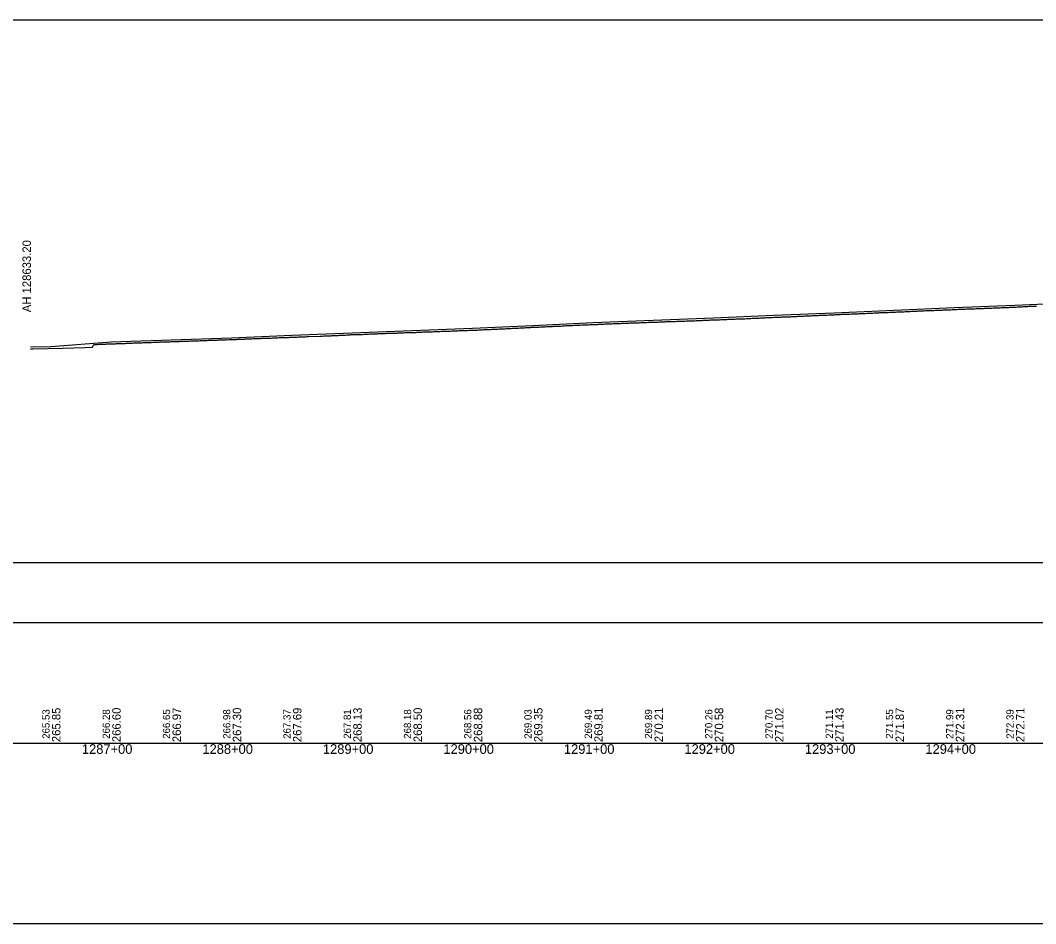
# Model space of a CAD drawing. Extents: x 2898 to 49495, y -15038 to -13538.
# Drawn here: x 18078 to 18921, y -15038 to -14288 of the extents above; entities that cross this region are included whole.
import ezdxf

# ---------------------------------------------------------------- set-up
doc = ezdxf.new("R2010")
doc.units = 0
for name, color, linetype in [('RD_DDB_Profile_EX', 7, 'Continuous'), ('RD_DDB_Profile_PR', 7, 'Continuous'), ('RD_DDB_StaTX', 7, 'Continuous'), ('RD_DDB_StripGrade', 7, 'Continuous'), ('RD_GPK_Profile_Cell', 7, 'Continuous'), ('RD_SHT_ShtClip', 7, 'Continuous')]:
    doc.layers.add(name, color=color, linetype=linetype)

msp = doc.modelspace()

# ---------------------------------------------------------------- linework, layer by layer
at = {"layer": 'RD_DDB_Profile_EX'}
for points in [[(18834.26, -14529.37), (18835.26, -14529.27), (18836.25, -14529.27), (18837.25, -14529.22), (18838.26, -14529.22), (18839.26, -14529.17), (18840.26, -14529.07), (18841.26, -14529.02), (18842.26, -14529.02), (18843.25, -14529.02), (18844.26, -14528.97), (18845.26, -14528.92), (18846.26, -14528.82), (18847.26, -14528.77), (18848.26, -14528.77), (18849.25, -14528.77), (18850.25, -14528.72), (18851.26, -14528.67), (18852.26, -14528.62), (18853.26, -14528.52), (18854.26, -14528.52), (18855.26, -14528.47), (18856.25, -14528.42), (18857.26, -14528.37), (18858.26, -14528.37), (18859.26, -14528.32), (18860.26, -14528.32), (18861.26, -14528.27), (18862.26, -14528.17), (18863.25, -14528.12), (18864.26, -14528.07), (18865.26, -14528.12), (18866.26, -14528.07), (18867.26, -14528.02), (18868.26, -14527.92), (18869.25, -14527.92), (18870.26, -14527.88), (18871.26, -14527.83), (18872.26, -14527.83), (18873.26, -14527.78), (18874.26, -14527.73), (18875.26, -14527.73), (18876.26, -14527.68), (18877.26, -14527.63), (18878.25, -14527.48), (18879.26, -14527.48), (18880.26, -14527.48), (18881.26, -14527.43), (18882.26, -14527.43), (18883.26, -14527.38), (18884.27, -14527.33), (18885.26, -14527.28), (18886.26, -14527.23), (18887.26, -14527.17), (18888.26, -14527.13), (18889.26, -14527.08), (18890.26, -14527.07), (18891.26, -14527.12), (18892.26, -14526.97), (18893.26, -14526.87), (18894.26, -14526.88), (18895.26, -14526.87), (18896.26, -14526.82), (18897.25, -14526.82), (18898.26, -14526.77), (18899.25, -14526.62), (18900.26, -14526.62), (18901.26, -14526.57), (18902.26, -14526.53), (18903.26, -14526.52), (18904.26, -14526.52), (18905.26, -14526.47), (18906.26, -14526.37), (18907.26, -14526.33), (18908.26, -14526.27), (18909.26, -14526.22), (18910.26, -14526.17), (18911.26, -14526.17), (18912.26, -14526.12), (18913.26, -14526.07), (18914.26, -14525.97), (18915.26, -14525.92), (18916.25, -14525.92), (18917.26, -14525.92), (18918.25, -14525.92), (18919.26, -14525.82), (18920.25, -14525.72), (18921.26, -14525.67)], [(18639.8, -14537.74), (18640.8, -14537.76), (18641.8, -14537.71), (18642.81, -14537.61), (18643.8, -14537.6), (18644.8, -14537.55), (18645.8, -14537.51), (18646.8, -14537.44), (18647.8, -14537.39), (18648.8, -14537.34), (18649.8, -14537.3), (18650.8, -14537.25), (18651.81, -14537.25), (18652.8, -14537.24), (18653.8, -14537.14), (18654.8, -14537.09), (18655.8, -14537.09), (18656.8, -14537.07), (18657.43, -14537.07), (18658.42, -14537.03), (18659.42, -14536.94), (18660.43, -14536.92), (18661.43, -14536.89), (18662.42, -14536.84), (18663.43, -14536.79), (18664.42, -14536.74), (18665.42, -14536.69), (18666.42, -14536.68), (18667.42, -14536.64), (18668.42, -14536.57), (18669.43, -14536.52), (18670.43, -14536.47), (18671.42, -14536.47), (18672.33, -14536.38), (18673.33, -14536.38), (18674.33, -14536.37), (18675.33, -14536.28), (18676.33, -14536.24), (18677.33, -14536.18), (18678.33, -14536.18), (18679.33, -14536.17), (18680.33, -14536.03), (18681.33, -14535.98), (18682.33, -14535.93), (18683.33, -14535.97), (18684.33, -14535.97), (18685.33, -14535.88), (18686.33, -14535.78), (18687.33, -14535.73), (18688.33, -14535.72), (18689.33, -14535.72), (18690.33, -14535.67), (18691.33, -14535.62), (18692.33, -14535.58), (18693.33, -14535.52), (18694.33, -14535.47), (18695.33, -14535.39), (18696.33, -14535.37), (18697.33, -14535.33), (18698.33, -14535.33), (18699.33, -14535.27), (18700.33, -14535.14), (18701.33, -14535.17), (18702.33, -14535.15), (18703.33, -14534.97), (18704.33, -14534.93), (18705.33, -14534.88), (18706.4, -14534.89), (18707.4, -14534.88), (18708.4, -14534.82), (18709.4, -14534.81), (18710.4, -14534.71), (18711.4, -14534.71), (18712.4, -14534.62), (18713.4, -14534.57), (18714.4, -14534.53), (18715.4, -14534.52), (18716.4, -14534.52), (18717.4, -14534.52), (18718.4, -14534.38), (18719.4, -14534.28), (18720.4, -14534.33), (18721.4, -14534.32), (18722.4, -14534.27), (18723.4, -14534.18), (18724.4, -14534.13), (18725.4, -14534.16), (18726.4, -14534.08), (18727.4, -14533.98), (18728.39, -14533.98), (18729.39, -14533.92), (18730.39, -14533.92), (18731.39, -14533.84), (18732.39, -14533.79), (18733.39, -14533.78), (18734.39, -14533.72), (18735.39, -14533.58), (18736.39, -14533.58), (18737.39, -14533.62), (18738.39, -14533.62), (18739.39, -14533.58)], [(18739.39, -14533.58), (18740.39, -14533.47), (18741.39, -14533.38), (18742.39, -14533.34), (18743.39, -14533.33), (18744.39, -14533.28), (18745.39, -14533.23), (18746.39, -14533.17), (18747.39, -14533.17), (18748.62, -14533.07), (18749.62, -14533.07), (18750.62, -14533.02), (18751.62, -14532.97), (18752.62, -14532.97), (18753.61, -14532.87), (18754.61, -14532.83), (18755.61, -14532.82), (18756.61, -14532.77), (18757.61, -14532.72), (18758.6, -14532.62), (18759.6, -14532.53), (18760.6, -14532.53), (18761.6, -14532.52), (18762.6, -14532.52), (18763.6, -14532.47), (18764.59, -14532.42), (18765.59, -14532.37), (18766.59, -14532.37), (18767.58, -14532.27), (18768.58, -14532.22), (18769.58, -14532.17), (18770.58, -14532.07), (18771.58, -14532.02), (18772.57, -14532.07), (18773.57, -14532.02), (18774.57, -14531.97), (18775.56, -14531.92), (18776.56, -14531.91), (18777.56, -14531.87), (18778.56, -14531.81), (18779.56, -14531.77), (18780.56, -14531.72), (18781.55, -14531.62), (18782.55, -14531.57), (18783.55, -14531.52), (18784.54, -14531.52), (18785.54, -14531.47), (18786.54, -14531.42), (18787.55, -14531.37), (18788.26, -14531.37), (18789.26, -14531.27), (18790.26, -14531.22), (18790.62, -14531.2), (18791.26, -14531.17), (18791.63, -14531.15), (18792.26, -14531.12), (18793.26, -14531.12), (18794.25, -14531.12), (18795.26, -14531.07), (18796.26, -14530.97), (18797.37, -14530.92), (18798.26, -14530.92), (18799.26, -14530.87), (18799.89, -14530.83), (18800.26, -14530.82), (18801.25, -14530.77), (18801.58, -14530.75), (18802.26, -14530.72), (18802.57, -14530.72), (18803.26, -14530.72), (18804.25, -14530.67), (18805.32, -14530.62), (18806.46, -14530.6), (18807.26, -14530.57), (18808.26, -14530.47), (18809.26, -14530.42), (18810.26, -14530.37), (18811.25, -14530.37), (18812.26, -14530.27), (18813.25, -14530.27), (18814.25, -14530.27), (18815.26, -14530.22), (18816.26, -14530.12), (18817.26, -14530.07), (18818.41, -14530.06), (18819.26, -14530.02), (18820.26, -14529.97), (18821.25, -14529.87), (18822.26, -14529.82), (18823.25, -14529.77), (18824.26, -14529.72), (18825.26, -14529.67), (18826.26, -14529.67), (18827.26, -14529.67), (18828.26, -14529.57), (18829.25, -14529.52), (18830.25, -14529.52), (18831.26, -14529.42), (18832.26, -14529.37), (18833.26, -14529.37), (18834.26, -14529.37)], [(18440.2, -14546.27), (18441.2, -14546.18), (18442.17, -14546.09), (18443.18, -14546.08), (18444.18, -14546.08), (18445.18, -14546.03), (18446.18, -14545.98), (18447.18, -14545.93), (18448.18, -14545.93), (18449.18, -14545.88), (18450.46, -14545.79), (18451.45, -14545.75), (18452.45, -14545.73), (18453.45, -14545.69), (18454.45, -14545.63), (18455.45, -14545.63), (18456.45, -14545.64), (18457.45, -14545.63), (18458.45, -14545.43), (18459.46, -14545.43), (18460.45, -14545.39), (18461.45, -14545.35), (18462.45, -14545.3), (18463.45, -14545.3), (18464.45, -14545.2), (18465.45, -14545.19), (18466.45, -14545.19), (18467.45, -14545.16), (18468.45, -14545.04), (18469.45, -14544.9), (18470.46, -14544.85), (18471.46, -14544.89), (18472.45, -14544.84), (18473.46, -14544.75), (18474.45, -14544.75), (18475.45, -14544.7), (18476.46, -14544.64), (18477.45, -14544.63), (18478.45, -14544.59), (18479.45, -14544.6), (18480.45, -14544.49), (18481.45, -14544.44), (18482.46, -14544.35), (18483.45, -14544.26), (18484.45, -14544.34), (18485.46, -14544.24), (18486.45, -14544.19), (18487.45, -14544.14), (18488.45, -14544.04), (18489.45, -14544.05), (18490.45, -14544.01), (18491.45, -14543.98), (18492.55, -14543.84), (18493.45, -14543.8), (18494.45, -14543.77), (18495.45, -14543.81), (18496.46, -14543.75), (18497.46, -14543.62), (18498.44, -14543.6), (18499.45, -14543.57), (18500.54, -14543.53), (18501.67, -14543.44), (18502.67, -14543.35), (18503.67, -14543.3), (18504.68, -14543.25), (18505.68, -14543.19), (18506.68, -14543.14), (18507.67, -14543.1), (18508.68, -14543.1), (18509.68, -14543), (18510.68, -14542.94), (18511.68, -14542.93), (18512.68, -14542.93), (18513.68, -14542.88), (18514.68, -14542.79), (18515.68, -14542.74), (18516.68, -14542.73), (18517.68, -14542.68), (18518.69, -14542.62), (18519.68, -14542.57), (18520.68, -14542.53), (18521.68, -14542.47), (18522.68, -14542.42), (18523.68, -14542.37), (18524.69, -14542.32), (18525.68, -14542.27), (18526.69, -14542.27), (18527.68, -14542.18), (18528.69, -14542.13), (18529.69, -14542.08), (18530.69, -14541.98), (18531.69, -14541.98), (18532.69, -14541.92), (18533.7, -14541.88), (18534.69, -14541.88), (18535.69, -14541.82), (18536.69, -14541.77), (18537.7, -14541.69), (18538.69, -14541.59), (18539.7, -14541.59), (18540.69, -14541.57)], [(18540.69, -14541.57), (18541.7, -14541.52), (18542.69, -14541.52), (18543.7, -14541.39), (18544.7, -14541.34), (18545.7, -14541.33), (18546.7, -14541.28), (18547.7, -14541.22), (18548.7, -14541.22), (18549.7, -14541.17), (18550.7, -14541.13), (18551.56, -14541.09), (18552.02, -14541.04), (18553.02, -14541.04), (18554.02, -14540.98), (18555.02, -14540.94), (18556.02, -14540.89), (18557.03, -14540.88), (18558.02, -14540.84), (18559.02, -14540.79), (18560.01, -14540.69), (18561.01, -14540.64), (18562.01, -14540.63), (18563.01, -14540.58), (18564.01, -14540.53), (18565, -14540.53), (18566.01, -14540.48), (18567.01, -14540.43), (18568, -14540.43), (18569, -14540.34), (18570.01, -14540.25), (18571.01, -14540.24), (18572.01, -14540.24), (18573.01, -14540.23), (18574, -14540.09), (18575, -14540.09), (18576.01, -14540.08), (18577, -14539.99), (18578, -14539.94), (18579.01, -14539.94), (18580, -14539.89), (18581.01, -14539.84), (18582.01, -14539.79), (18583, -14539.79), (18584, -14539.74), (18585, -14539.73), (18586, -14539.68), (18587, -14539.64), (18588.01, -14539.63), (18589, -14539.59), (18590, -14539.54), (18591, -14539.53), (18592, -14539.49), (18593, -14539.44), (18594, -14539.39), (18595, -14539.34), (18596, -14539.3), (18597, -14539.29), (18598, -14539.24), (18599, -14539.15), (18600, -14539.14), (18601, -14539.09), (18602, -14539.04), (18602.82, -14539), (18603.82, -14539), (18604.82, -14538.95), (18605.83, -14538.99), (18606.82, -14538.98), (18607.83, -14538.9), (18608.82, -14538.85), (18609.82, -14538.85), (18610.82, -14538.79), (18611.82, -14538.78), (18612.82, -14538.69), (18613.82, -14538.65), (18614.83, -14538.64), (18615.8, -14538.65), (18616.81, -14538.62), (18617.8, -14538.59), (18618.8, -14538.54), (18619.8, -14538.44), (18620.8, -14538.39), (18621.8, -14538.39), (18622.8, -14538.35), (18623.8, -14538.35), (18624.8, -14538.3), (18625.81, -14538.28), (18626.8, -14538.23), (18627.8, -14538.19), (18628.8, -14538.14), (18629.8, -14538.13), (18630.8, -14538.08), (18631.8, -14538.04), (18632.8, -14538.08), (18633.81, -14538.03), (18634.8, -14537.94), (18635.8, -14537.85), (18636.81, -14537.84), (18637.8, -14537.88), (18638.8, -14537.79), (18639.8, -14537.74)], [(18231.26, -14554.22), (18232.26, -14554.22), (18233.26, -14554.17), (18234.26, -14554.12), (18235.26, -14554.07), (18236.26, -14554.07), (18237.26, -14554.12), (18238.26, -14554.07), (18239.26, -14553.92), (18240.26, -14554.01), (18241.31, -14554.01), (18242.31, -14553.82), (18243.3, -14553.82), (18244.31, -14553.77), (18245.31, -14553.82), (18246.3, -14553.72), (18247.31, -14553.67), (18248.31, -14553.67), (18249.31, -14553.57), (18250.31, -14553.62), (18251.31, -14553.57), (18252.31, -14553.52), (18253.31, -14553.57), (18254.31, -14553.52), (18255.3, -14553.37), (18256.3, -14553.37), (18257.31, -14553.42), (18258.31, -14553.27), (18259.31, -14553.17), (18260.31, -14553.17), (18261.31, -14553.12), (18262.3, -14553.12), (18263.31, -14553.12), (18264.31, -14553.07), (18265.3, -14553.02), (18266.31, -14553.02), (18267.31, -14553.02), (18268.31, -14552.97), (18269.31, -14552.92), (18270.31, -14552.87), (18271.31, -14552.77), (18272.3, -14552.72), (18273.31, -14552.72), (18274.3, -14552.72), (18275.3, -14552.67), (18276.31, -14552.62), (18277.31, -14552.52), (18278.31, -14552.47), (18279.31, -14552.47), (18280.31, -14552.47), (18281.3, -14552.37), (18282.31, -14552.37), (18283.3, -14552.37), (18284.3, -14552.32), (18285.31, -14552.27), (18286.31, -14552.22), (18287.31, -14552.17), (18287.87, -14552.12), (18288.86, -14552.17), (18289.87, -14552.17), (18290.87, -14552.07), (18291.87, -14551.97), (18292.87, -14551.92), (18293.86, -14551.87), (18294.87, -14551.87), (18295.86, -14551.87), (18296.87, -14551.82), (18297.87, -14551.72), (18298.87, -14551.67), (18299.87, -14551.67), (18300.87, -14551.67), (18301.87, -14551.62), (18302.87, -14551.62), (18303.87, -14551.57), (18304.87, -14551.52), (18305.87, -14551.47), (18306.87, -14551.42), (18307.87, -14551.42), (18308.87, -14551.32), (18309.87, -14551.37), (18310.87, -14551.32), (18311.87, -14551.22), (18312.86, -14551.22), (18313.87, -14551.22), (18314.87, -14551.17), (18315.87, -14551.07), (18316.87, -14551.02), (18326.87, -14550.62), (18327.87, -14550.57), (18328.87, -14550.57), (18329.87, -14550.52), (18330.87, -14550.42), (18331.87, -14550.42), (18332.87, -14550.42), (18333.87, -14550.42), (18334.87, -14550.37), (18335.99, -14550.32), (18336.99, -14550.22), (18337.99, -14550.17), (18338.99, -14550.12), (18339.99, -14550.07)], [(18339.99, -14550.07), (18340.99, -14550.02), (18342, -14550.02), (18343, -14549.97), (18344, -14549.92), (18345, -14549.87), (18346, -14549.87), (18347, -14549.82), (18348, -14549.77), (18349, -14549.72), (18350, -14549.67), (18351, -14549.62), (18352, -14549.47), (18353, -14549.43), (18354.11, -14549.44), (18355.11, -14549.43), (18356.11, -14549.42), (18357.12, -14549.33), (18358.11, -14549.33), (18359.11, -14549.28), (18360.11, -14549.27), (18361.11, -14549.27), (18362.11, -14549.22), (18363.11, -14549.13), (18364.11, -14549.12), (18365.11, -14549.07), (18366.11, -14548.97), (18367.11, -14548.92), (18368.11, -14548.87), (18369.11, -14548.83), (18370.11, -14548.78), (18371.11, -14548.73), (18372.11, -14548.68), (18373.11, -14548.68), (18374.11, -14548.63), (18375.11, -14548.62), (18376.11, -14548.58), (18377.11, -14548.48), (18378.16, -14548.47), (18379.15, -14548.47), (18380.15, -14548.47), (18381.16, -14548.47), (18382.15, -14548.28), (18383.15, -14548.27), (18384.15, -14548.27), (18385.15, -14548.22), (18386.16, -14548.17), (18387.16, -14548.12), (18388.15, -14548.12), (18389.15, -14548.07), (18390.16, -14548.07), (18391.15, -14548.02), (18392.15, -14547.97), (18393.15, -14547.97), (18394.15, -14547.87), (18395.15, -14547.82), (18396.15, -14547.82), (18397.15, -14547.77), (18398.15, -14547.77), (18399.14, -14547.77), (18400.19, -14547.67), (18401.19, -14547.62), (18402.19, -14547.62), (18403.19, -14547.57), (18404.19, -14547.52), (18405.19, -14547.52), (18406.19, -14547.52), (18407.2, -14547.37), (18408.19, -14547.37), (18409.2, -14547.37), (18410.19, -14547.32), (18411.2, -14547.27), (18412.19, -14547.18), (18413.19, -14547.17), (18414.19, -14547.12), (18415.19, -14547.07), (18416.2, -14547.07), (18417.2, -14547.07), (18418.2, -14547.02), (18419.19, -14546.98), (18420.2, -14546.97), (18421.19, -14546.92), (18422.19, -14546.82), (18423.2, -14546.78), (18424.2, -14546.73), (18425.2, -14546.73), (18426.2, -14546.73), (18427.2, -14546.68), (18428.2, -14546.63), (18429.19, -14546.57), (18430.2, -14546.57), (18431.2, -14546.53), (18432.2, -14546.52), (18433.2, -14546.52), (18434.2, -14546.47), (18435.2, -14546.42), (18436.19, -14546.38), (18437.2, -14546.33), (18438.19, -14546.28), (18439.2, -14546.27), (18440.2, -14546.27)], [(18086.58, -14561.31), (18087.98, -14561.27), (18088.37, -14561.26), (18113.15, -14560.54), (18131.89, -14559.99), (18137.99, -14559.8), (18138.97, -14557.67), (18139.96, -14557.67), (18140.96, -14557.62), (18141.96, -14557.57), (18142.96, -14557.47), (18143.96, -14557.47), (18144.97, -14557.37), (18145.96, -14557.37), (18146.97, -14557.42), (18147.96, -14557.32), (18148.96, -14557.27), (18149.96, -14557.17), (18150.96, -14557.17), (18151.96, -14557.12), (18152.97, -14557.07), (18153.96, -14557.02), (18154.97, -14557.02), (18155.96, -14556.97), (18156.96, -14556.97), (18157.96, -14556.92), (18158.96, -14556.92), (18159.96, -14556.87), (18160.97, -14556.82), (18161.96, -14556.77), (18162.97, -14556.77), (18163.96, -14556.77), (18165.2, -14556.65), (18165.96, -14556.62), (18166.42, -14556.62), (18166.96, -14556.62), (18167.96, -14556.52), (18168.97, -14556.47), (18169.96, -14556.47), (18170.97, -14556.42), (18171.97, -14556.37), (18172.96, -14556.27), (18173.96, -14556.27), (18174.96, -14556.22), (18175.96, -14556.17), (18176.97, -14556.17), (18177.96, -14556.17), (18178.96, -14556.12), (18179.97, -14556.07), (18180.96, -14556.02), (18181.96, -14555.97), (18182.96, -14555.97), (18183.96, -14555.97), (18184.97, -14556.07), (18185.96, -14555.82), (18186.96, -14555.82), (18187.97, -14555.77), (18188.96, -14555.77), (18189.96, -14555.77), (18190.96, -14555.72), (18191.96, -14555.62), (18193.26, -14555.57), (18194.26, -14555.52), (18195.26, -14555.52), (18196.26, -14555.47), (18197.26, -14555.42), (18198.26, -14555.42), (18199.25, -14555.37), (18200.26, -14555.32), (18201.25, -14555.32), (18202.26, -14555.27), (18203.25, -14555.22), (18204.26, -14555.17), (18205.26, -14555.12), (18206.26, -14555.12), (18207.26, -14555.17), (18208.26, -14555.12), (18209.26, -14555.07), (18210.26, -14555.02), (18211.25, -14554.92), (18212.26, -14554.92), (18213.25, -14554.87), (18213.67, -14554.87), (18214.26, -14554.87), (18215.37, -14554.77), (18216.25, -14554.77), (18217.26, -14554.82), (18218.25, -14554.77), (18219.26, -14554.67), (18220.25, -14554.57), (18221.26, -14554.62), (18222.26, -14554.62), (18223.26, -14554.57), (18224.26, -14554.52), (18225.26, -14554.47), (18226.26, -14554.47), (18227.26, -14554.42), (18228.25, -14554.37), (18229.26, -14554.32), (18230.26, -14554.22), (18231.26, -14554.22)]]:
    msp.add_lwpolyline(points, dxfattribs=at)
at = {"layer": 'RD_DDB_Profile_PR'}
msp.add_lwpolyline([(18086.58, -14559.6), (18103.38, -14559.22), (18153.38, -14555.45), (18203.38, -14553.61), (18253.38, -14551.96), (18303.38, -14549.99), (18353.38, -14547.83), (18403.38, -14545.96), (18453.38, -14544.09), (18503.38, -14541.71), (18553.38, -14539.42), (18603.38, -14537.4), (18653.38, -14535.58), (18703.38, -14533.37), (18753.38, -14531.29), (18803.38, -14529.11), (18853.38, -14526.92), (18903.38, -14524.92), (18953.38, -14522.72)], dxfattribs=at)
at = {"layer": 'RD_GPK_Profile_Cell'}
msp.add_line((2976.05, -14888.47), (48721.13, -14888.47), dxfattribs=at)
at = {"layer": 'RD_SHT_ShtClip'}
for points in [[(17976.38, -14288.47), (17976.38, -14788.47), (19475.38, -14788.47), (19475.38, -14788.47), (19475.38, -14288.47), (19475.38, -14288.47)], [(17956.38, -14738.47), (19495.38, -14738.47), (19495.38, -15038.47), (17956.38, -15038.47)]]:
    msp.add_lwpolyline(points, close=True, dxfattribs=at)

# ---------------------------------------------------------------- texts
at = {"layer": 'RD_DDB_Profile_PR'}
msp.add_text('AH 128633.20', height=7, rotation=90, dxfattribs=at).set_placement((18086.88, -14530.8))
at = {"layer": 'RD_DDB_StaTX'}
for s, p in [('1287+00', (18129.18, -14897.47)), ('1288+00', (18229.18, -14897.47)), ('1289+00', (18329.18, -14897.47)), ('1290+00', (18429.18, -14897.47)), ('1291+00', (18529.18, -14897.47)), ('1292+00', (18629.18, -14897.47)), ('1293+00', (18729.18, -14897.47)), ('1294+00', (18829.18, -14897.47))]:
    msp.add_text(s, height=8, dxfattribs=at).set_placement(p)
at = {"layer": 'RD_DDB_StripGrade'}
for s, height, p in [('265.53', 6, (18102.38, -14884.98)), ('265.85', 7, (18111.38, -14887.72)), ('266.28', 6, (18152.38, -14884.98)), ('266.60', 7, (18161.38, -14887.72)), ('266.65', 6, (18202.38, -14884.98)), ('266.97', 7, (18211.38, -14887.72)), ('266.98', 6, (18252.38, -14884.98)), ('267.30', 7, (18261.38, -14887.72)), ('267.37', 6, (18302.38, -14884.98)), ('267.69', 7, (18311.38, -14887.72)), ('267.81', 6, (18352.38, -14884.98)), ('268.13', 7, (18361.38, -14887.72)), ('268.18', 6, (18402.38, -14884.98)), ('268.50', 7, (18411.38, -14887.72)), ('268.56', 6, (18452.38, -14884.98)), ('268.88', 7, (18461.38, -14887.72)), ('269.03', 6, (18502.38, -14884.98)), ('269.35', 7, (18511.38, -14887.72)), ('269.49', 6, (18552.38, -14884.98)), ('269.81', 7, (18561.38, -14887.72)), ('269.89', 6, (18602.38, -14884.98)), ('270.21', 7, (18611.38, -14887.72)), ('270.26', 6, (18652.38, -14884.98)), ('270.58', 7, (18661.38, -14887.72)), ('270.70', 6, (18702.38, -14884.98)), ('271.02', 7, (18711.38, -14887.72)), ('271.11', 6, (18752.38, -14884.98)), ('271.43', 7, (18761.38, -14887.72)), ('271.55', 6, (18802.38, -14884.98)), ('271.87', 7, (18811.38, -14887.72)), ('271.99', 6, (18852.38, -14884.98)), ('272.31', 7, (18861.38, -14887.72)), ('272.39', 6, (18902.38, -14884.98)), ('272.71', 7, (18911.38, -14887.72))]:
    msp.add_text(s, height=height, rotation=90, dxfattribs=at).set_placement(p)

doc.saveas('drawing.dxf')
